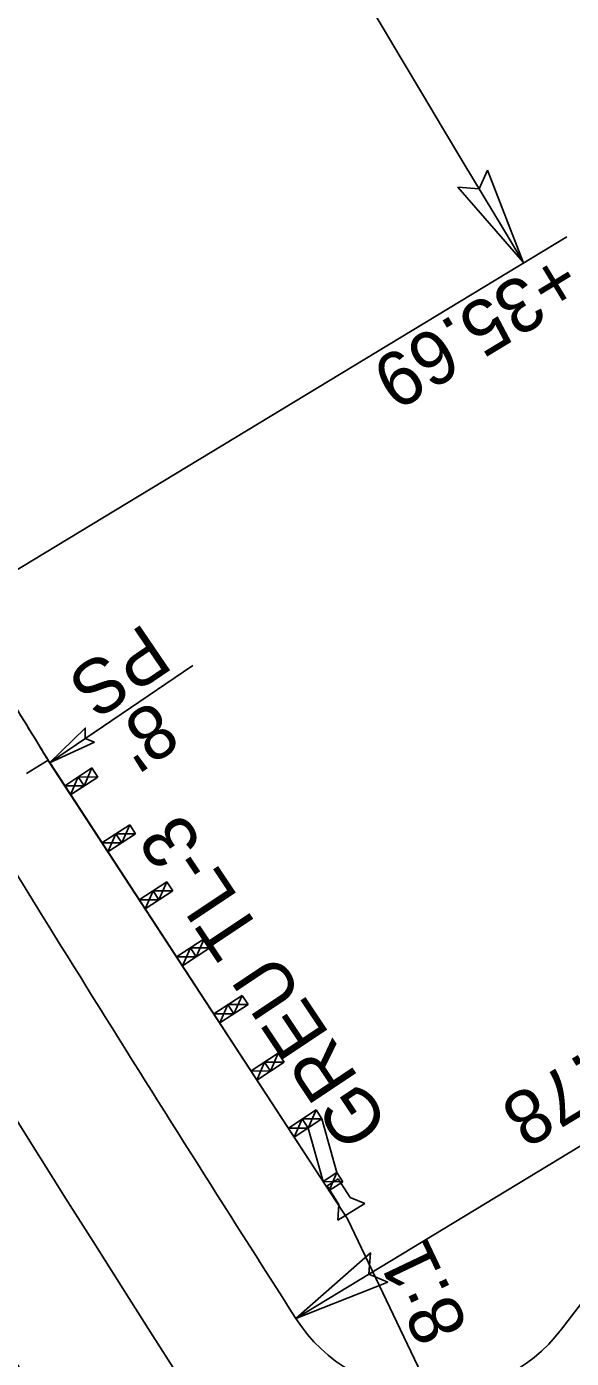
# Model space of a CAD drawing. Extents: x 472216 to 481979, y 489069 to 507339.
# Drawn here: x 476192.3 to 476242.6, y 501260.2 to 501383.3 of the extents above; entities that cross this region are included whole.
import ezdxf

# ---------------------------------------------------------------- set-up
doc = ezdxf.new("R2010")
doc.units = 0
for name, color, linetype in [('Prop Drainage Structure Outlet Berm Ditch 850 10 CELL', 7, 'Continuous'), ('Prop Drainage Structure Pipe CSP 15in', 7, 'Continuous'), ('Prop Drainage Structure Pipe Plug CELL', 7, 'Continuous'), ('Prop Drainage Structure Pipe RCP 24in Class III Label', 7, 'Continuous'), ('Prop Erosion Embankment Toe Protection CELL', 7, 'Continuous'), ('Sheet Block Revision CELL', 7, 'Continuous'), ('Sheet North Arrow Point CELL', 7, 'Continuous'), ('Sheet Plot Border Inside CELL', 7, 'Continuous')]:
    doc.layers.add(name, color=color, linetype=linetype)

msp = doc.modelspace()

# ---------------------------------------------------------------- linework, layer by layer
at = {"layer": 'Prop Drainage Structure Outlet Berm Ditch 850 10 CELL'}
for points in [[(476234.85, 501370.06), (476238.17, 501361.55), (476232.13, 501368.47), (476234.09, 501368.32)], [(476198.54, 501317.15), (476194.38, 501315.26), (476197.68, 501318.47), (476197.65, 501317.49)], [(476225.64, 501267.22), (476217.14, 501263.87), (476224.05, 501269.94), (476223.9, 501267.97)]]:
    msp.add_lwpolyline(points, close=True, dxfattribs=at)
at = {"layer": 'Prop Drainage Structure Pipe Plug CELL'}
for p, q in [((476194.39, 501315.27), (476219.95, 501276.12)), ((476195.78, 501313.14), (476198.29, 501314.78)), ((476197.58, 501313.12), (476198.29, 501314.78)), ((476198.29, 501314.78), (476198.84, 501313.94)), ((476195.78, 501313.14), (476196.32, 501312.3)), ((476197.58, 501313.12), (476195.78, 501313.14)), ((476197.03, 501313.96), (476196.32, 501312.3)), ((476196.32, 501312.3), (476198.84, 501313.94)), ((476196.32, 501312.3), (476197.58, 501313.12)), ((476197.03, 501313.96), (476197.58, 501313.12)), ((476198.84, 501313.94), (476197.03, 501313.96)), ((476199.22, 501307.86), (476201.78, 501309.53)), ((476201.05, 501307.86), (476201.78, 501309.53)), ((476201.78, 501309.53), (476202.33, 501308.69)), ((476200.5, 501308.7), (476199.77, 501307.02)), ((476199.77, 501307.02), (476202.33, 501308.69)), ((476200.5, 501308.7), (476201.05, 501307.86)), ((476202.33, 501308.69), (476200.5, 501308.7)), ((476199.22, 501307.86), (476201.05, 501307.86)), ((476202.67, 501302.59), (476205.22, 501304.25)), ((476204.49, 501302.58), (476205.22, 501304.25)), ((476205.22, 501304.25), (476205.77, 501303.41)), ((476203.95, 501303.42), (476203.22, 501301.75)), ((476203.22, 501301.75), (476205.77, 501303.41)), ((476203.95, 501303.42), (476204.49, 501302.58)), ((476205.77, 501303.41), (476203.95, 501303.42)), ((476202.67, 501302.59), (476204.49, 501302.58)), ((476206.11, 501297.31), (476208.66, 501298.97)), ((476207.39, 501298.14), (476206.66, 501296.47)), ((476206.66, 501296.47), (476209.2, 501298.13)), ((476207.39, 501298.14), (476207.93, 501297.3)), ((476209.2, 501298.13), (476207.39, 501298.14)), ((476207.93, 501297.3), (476208.66, 501298.97)), ((476208.66, 501298.97), (476209.2, 501298.13)), ((476206.11, 501297.31), (476206.66, 501296.47)), ((476206.11, 501297.31), (476207.93, 501297.3)), ((476209.56, 501292.03), (476212.19, 501293.75)), ((476211.42, 501292.05), (476212.19, 501293.75)), ((476212.19, 501293.75), (476212.73, 501292.91)), ((476209.56, 501292.03), (476211.42, 501292.05)), ((476210.11, 501291.2), (476212.73, 501292.91)), ((476210.87, 501292.89), (476210.11, 501291.2)), ((476212.73, 501292.91), (476210.87, 501292.89)), ((476210.87, 501292.89), (476211.42, 501292.05)), ((476213.01, 501286.76), (476215.52, 501288.4)), ((476214.81, 501286.74), (476215.52, 501288.4)), ((476215.52, 501288.4), (476216.06, 501287.56)), ((476214.26, 501287.58), (476213.55, 501285.92)), ((476213.55, 501285.92), (476216.06, 501287.56)), ((476214.26, 501287.58), (476214.81, 501286.74)), ((476216.06, 501287.56), (476214.26, 501287.58)), ((476213.01, 501286.76), (476214.81, 501286.74)), ((476216.45, 501281.48), (476219.02, 501283.16)), ((476217, 501280.65), (476219.56, 501282.32)), ((476217.73, 501282.32), (476217, 501280.65)), ((476217.73, 501282.32), (476218.28, 501281.48)), ((476219.56, 501282.32), (476217.73, 501282.32)), ((476218.28, 501281.48), (476219.02, 501283.16)), ((476219.02, 501283.16), (476219.56, 501282.32)), ((476219.56, 501282.32), (476220.93, 501277.36)), ((476216.45, 501281.48), (476218.28, 501281.48)), ((476218.28, 501281.48), (476219.68, 501276.54)), ((476219.68, 501276.54), (476220.93, 501277.36)), ((476220.23, 501275.7), (476220.93, 501277.36)), ((476220.93, 501277.36), (476221.21, 501276.94)), ((476220.93, 501277.36), (476221.48, 501276.52)), ((476221.48, 501276.52), (476219.68, 501276.54)), ((476220.55, 501276.46), (476220.03, 501276.14)), ((476220.03, 501276.14), (476221.12, 501274.4)), ((476220.23, 501275.7), (476221.48, 501276.52)), ((476221.07, 501276.79), (476220.55, 501276.46)), ((476222.16, 501275.05), (476221.07, 501276.79)), ((476223.51, 501274.51), (476222.16, 501275.05)), ((476221.02, 501272.95), (476223.51, 501274.51)), ((476221.12, 501274.4), (476221.02, 501272.95))]:
    msp.add_line(p, q, dxfattribs=at)
at = {"layer": 'Prop Drainage Structure Pipe RCP 24in Class III Label'}
for p, q in [((476194.24, 501315.49), (476192.25, 501314.28)), ((476241.71, 501262.87), (476245.52, 501267.87))]:
    msp.add_line(p, q, dxfattribs=at)
for centre, radius, start, end in [((478615.62, 502799.59), 2848, 211.17411, 212.6311), ((478615.62, 502799.59), 2872, 211.17405, 212.79272), ((478615.62, 502799.59), 2872, 211.17405, 212.77227), ((476229.78, 501271.96), 15, 212.6311, 322.6937)]:
    msp.add_arc(centre, radius, start, end, dxfattribs=at)
at = {"layer": 'Prop Erosion Embankment Toe Protection CELL'}
for p in [(476194.29, 501315.42), (476229.61, 501256.96)]:
    msp.add_line(p, (476221.93, 501273.09), dxfattribs=at)
for radius, start, end in [(2840, 211.17617, 211.51031), (2877, 211.17527, 212.96504)]:
    msp.add_arc((478615.62, 502799.59), radius, start, end, dxfattribs=at)
at = {"layer": 'Sheet Block Revision CELL'}
for p, q in [((476187.55, 501330.81), (476242.21, 501363.88)), ((476207.61, 501324.26), (476194.38, 501315.26)), ((476217.14, 501263.87), (476268.62, 501295.12))]:
    msp.add_line(p, q, dxfattribs=at)
msp.add_arc((478685.2, 502841.98), 2860, 206.50247, 211.17553, dxfattribs=at)
at = {"layer": 'Sheet North Arrow Point CELL'}
msp.add_arc((478615.62, 502799.59), 2860, 203.81642, 228.24762, dxfattribs=at)
at = {"layer": 'Sheet Plot Border Inside CELL'}
msp.add_arc((478615.62, 502799.59), 2840, 211.18124, 211.51028, dxfattribs=at)

# ---------------------------------------------------------------- texts
at = {"layer": 'Prop Drainage Structure Pipe CSP 15in'}
for s, rotation, p in [('+35.69', 211.24, (476241.47, 501362.69)), ('PS', 214.233, (476203.16, 501328.26)), ("8'", 214.233, (476203.99, 501321.16)), ('+62.78', 211.24, (476253.43, 501294.43)), ('8:1', 115.4636, (476233.17, 501263.07))]:
    msp.add_text(s, height=5, rotation=rotation, dxfattribs=at).set_placement(p)
at = {"layer": 'Prop Drainage Structure Pipe Plug CELL'}
msp.add_text('GREU TL-3', height=5, rotation=123.6929, dxfattribs=at).set_placement((476225.91, 501281.78))

doc.saveas('drawing.dxf')
